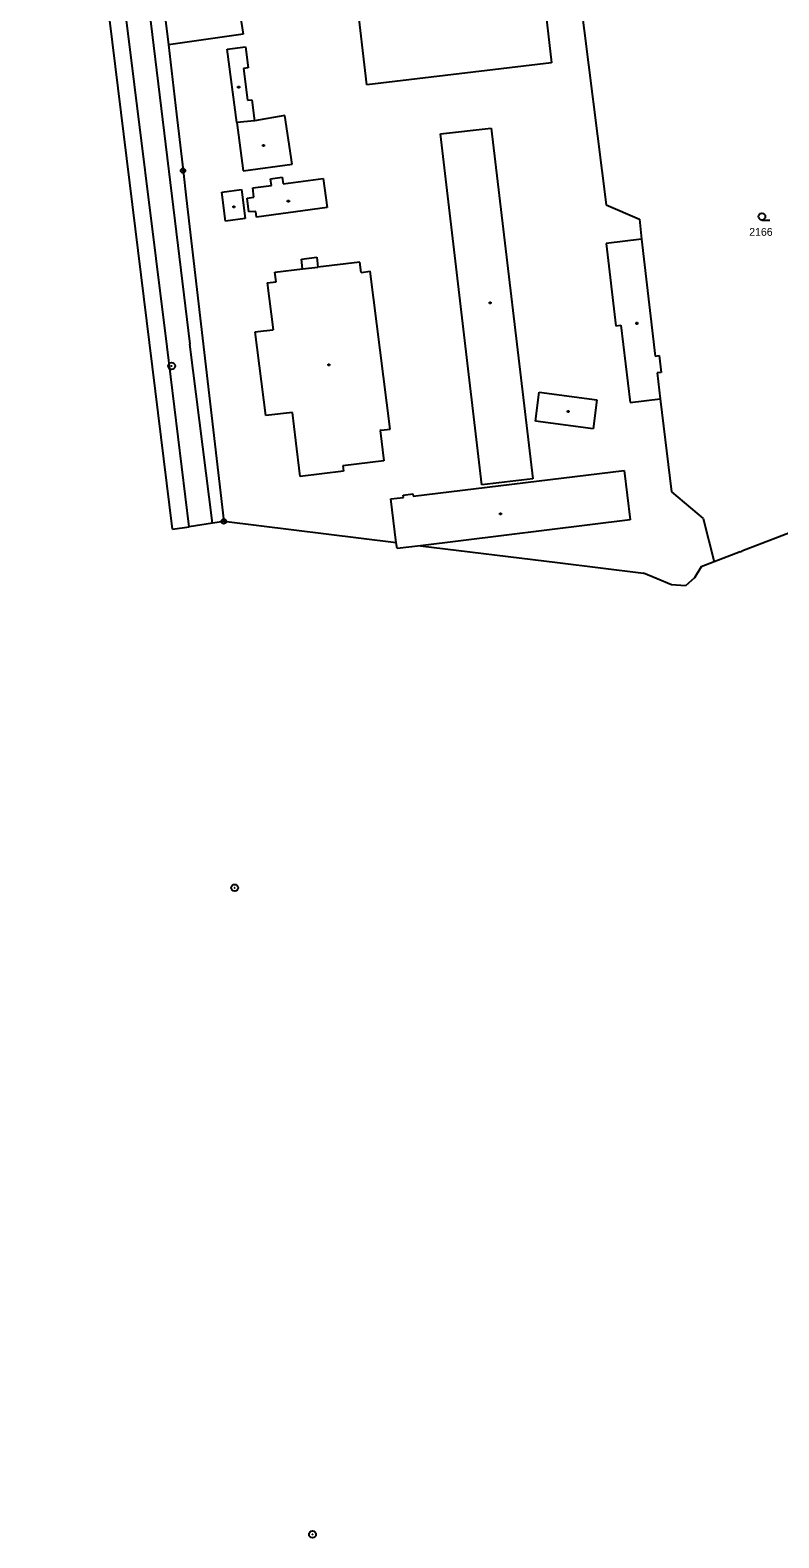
# Model space of a CAD drawing. Extents: x -795483 to -789093, y -1112258 to -1108741.
# Drawn here: x -791769.3 to -791607.3, y -1111747 to -1111421 of the extents above; entities that cross this region are included whole.
import ezdxf

# ---------------------------------------------------------------- set-up
doc = ezdxf.new("R2010")
doc.units = 0
for name, color, linetype in [('Vrstva 1', 7, 'Continuous'), ('Vrstva 14', 7, 'Continuous'), ('Vrstva 2', 7, 'Continuous'), ('Vrstva 23', 7, 'Continuous'), ('Vrstva 25', 7, 'Continuous'), ('Vrstva 28', 7, 'Continuous'), ('Vrstva 3', 7, 'Continuous'), ('Vrstva 4', 7, 'Continuous')]:
    doc.layers.add(name, color=color, linetype=linetype)

msp = doc.modelspace()

# ---------------------------------------------------------------- linework, layer by layer
at = {"layer": 'Vrstva 1'}
for p, q in [((-791744.16, -1111384.45), (-791739.38, -1111424.13)), ((-791653.57, -1111388.05), (-791644.62, -1111458.76)), ((-791723.95, -1111417.3), (-791723.17, -1111421.87)), ((-791723.17, -1111421.87), (-791739.38, -1111424.13)), ((-791739.38, -1111424.13), (-791737.64, -1111439.15)), ((-791737.64, -1111439.15), (-791736.22, -1111451.36)), ((-791736.22, -1111451.36), (-791735.54, -1111457.24)), ((-791735.54, -1111457.24), (-791727.4, -1111527.22)), ((-791644.62, -1111458.76), (-791637.47, -1111461.87)), ((-791637.47, -1111461.87), (-791637.02, -1111466.18)), ((-791637.02, -1111466.18), (-791634.04, -1111491.46)), ((-791634.04, -1111491.46), (-791633.18, -1111491.36)), ((-791633.18, -1111491.36), (-791632.76, -1111494.98)), ((-791632.76, -1111494.98), (-791633.61, -1111495.09)), ((-791633.61, -1111495.09), (-791632.95, -1111500.71)), ((-791632.95, -1111500.71), (-791630.52, -1111520.82)), ((-791630.52, -1111520.82), (-791623.66, -1111526.59)), ((-791623.66, -1111526.59), (-791621.26, -1111535.95))]:
    msp.add_line(p, q, dxfattribs=at)
at = {"layer": 'Vrstva 2'}
for p, q in [((-791769.19, -1111205.07), (-791734.76, -1111488.89)), ((-791739.62, -1111489.46), (-791769.3, -1111251.83)), ((-791660.16, -1111395.95), (-791656.45, -1111428.01)), ((-791696.42, -1111432.77), (-791700.24, -1111400.72)), ((-791726.68, -1111425.07), (-791722.71, -1111424.61)), ((-791724.58, -1111440.91), (-791726.68, -1111425.07)), ((-791722.71, -1111424.61), (-791722.15, -1111429.12)), ((-791722.15, -1111429.12), (-791723.14, -1111429.24)), ((-791723.14, -1111429.24), (-791722.29, -1111436.14)), ((-791656.45, -1111428.01), (-791696.42, -1111432.77)), ((-791722.29, -1111436.14), (-791721.3, -1111436.01)), ((-791721.3, -1111436.01), (-791720.74, -1111440.57)), ((-791714.2, -1111439.4), (-791720.74, -1111440.57)), ((-791712.61, -1111449.97), (-791714.2, -1111439.4)), ((-791720.74, -1111440.57), (-791724.58, -1111440.91)), ((-791724.58, -1111440.91), (-791723.18, -1111451.38)), ((-791680.48, -1111443.43), (-791669.53, -1111442.14)), ((-791669.53, -1111442.14), (-791660.53, -1111517.97)), ((-791671.53, -1111519.27), (-791680.48, -1111443.43)), ((-791723.18, -1111451.38), (-791712.61, -1111449.97)), ((-791717.28, -1111453.15), (-791714.77, -1111452.79)), ((-791717.09, -1111454.56), (-791717.28, -1111453.15)), ((-791714.77, -1111452.79), (-791714.58, -1111454.22)), ((-791714.58, -1111454.22), (-791705.88, -1111453.06)), ((-791705.88, -1111453.06), (-791705.02, -1111459.35)), ((-791727.83, -1111455.99), (-791723.59, -1111455.43)), ((-791727.05, -1111462.29), (-791727.83, -1111455.99)), ((-791723.59, -1111455.43), (-791722.77, -1111461.72)), ((-791721.13, -1111455.1), (-791717.09, -1111454.56)), ((-791720.86, -1111457.1), (-791721.13, -1111455.1)), ((-791722.35, -1111457.29), (-791720.86, -1111457.1)), ((-791721.98, -1111460.28), (-791722.35, -1111457.29)), ((-791705.02, -1111459.35), (-791720.32, -1111461.39)), ((-791722.77, -1111461.72), (-791727.05, -1111462.29)), ((-791720.48, -1111460.17), (-791721.98, -1111460.28)), ((-791720.32, -1111461.39), (-791720.48, -1111460.17)), ((-791637.02, -1111466.18), (-791644.64, -1111467.13)), ((-791644.64, -1111467.13), (-791642.54, -1111484.92)), ((-791716.32, -1111473.3), (-791710.34, -1111472.59)), ((-791710.6, -1111470.47), (-791707.27, -1111470.06)), ((-791710.34, -1111472.59), (-791710.6, -1111470.47)), ((-791710.34, -1111472.59), (-791707.02, -1111472.2)), ((-791707.27, -1111470.06), (-791707.02, -1111472.2)), ((-791697.93, -1111471.13), (-791707.02, -1111472.2)), ((-791697.65, -1111473.36), (-791697.93, -1111471.13)), ((-791718, -1111475.63), (-791716.06, -1111475.39)), ((-791718, -1111475.63), (-791716.73, -1111485.76)), ((-791716.06, -1111475.39), (-791716.32, -1111473.3)), ((-791697.65, -1111473.36), (-791695.71, -1111473.12)), ((-791691.41, -1111507.25), (-791695.71, -1111473.12)), ((-791718.8, -1111486.02), (-791716.73, -1111485.76)), ((-791642.54, -1111484.92), (-791641.47, -1111484.8)), ((-791641.47, -1111484.8), (-791639.49, -1111501.47)), ((-791729.85, -1111527.59), (-791734.76, -1111488.89)), ((-791720.57, -1111486.24), (-791718.8, -1111486.02)), ((-791718.28, -1111504.32), (-791720.57, -1111486.24)), ((-791734.87, -1111528.35), (-791739.62, -1111489.46)), ((-791659.94, -1111505.53), (-791659.12, -1111499.29)), ((-791659.12, -1111499.29), (-791646.64, -1111500.92)), ((-791646.64, -1111500.92), (-791647.46, -1111507.18)), ((-791639.49, -1111501.47), (-791632.95, -1111500.71)), ((-791712.54, -1111503.63), (-791718.28, -1111504.32)), ((-791711.81, -1111509.74), (-791712.54, -1111503.63)), ((-791693.35, -1111507.49), (-791693.57, -1111507.52)), ((-791693.57, -1111507.52), (-791692.76, -1111514.08)), ((-791693.35, -1111507.49), (-791691.41, -1111507.25)), ((-791647.46, -1111507.18), (-791659.94, -1111505.53)), ((-791710.88, -1111517.52), (-791711.81, -1111509.74)), ((-791692.76, -1111514.08), (-791701.67, -1111515.17)), ((-791701.52, -1111516.37), (-791710.88, -1111517.52)), ((-791701.67, -1111515.17), (-791701.52, -1111516.37)), ((-791686.45, -1111521.77), (-791640.76, -1111516.19)), ((-791660.53, -1111517.97), (-791671.53, -1111519.27)), ((-791640.76, -1111516.19), (-791639.45, -1111526.89)), ((-791688.59, -1111521.52), (-791686.52, -1111521.26)), ((-791688.53, -1111522.02), (-791688.59, -1111521.52)), ((-791686.52, -1111521.26), (-791686.45, -1111521.77)), ((-791691.22, -1111522.35), (-791688.53, -1111522.02)), ((-791690.06, -1111531.82), (-791691.22, -1111522.35)), ((-791639.45, -1111526.89), (-791684.82, -1111532.47))]:
    msp.add_line(p, q, dxfattribs=at)
at = {"layer": 'Vrstva 23'}
msp.add_line((-791610.96, -1111462.03), (-791609.21, -1111462.03), dxfattribs=at)
msp.add_circle((-791610.96, -1111461.28), 0.75, dxfattribs=at)
at = {"layer": 'Vrstva 25'}
for p, q in [((-791724.32, -1111433.14), (-791724.02, -1111433.14)), ((-791724.32, -1111433.44), (-791724.32, -1111433.14)), ((-791724.02, -1111433.44), (-791724.32, -1111433.44)), ((-791724.02, -1111433.14), (-791724.02, -1111433.44)), ((-791718.95, -1111445.75), (-791718.65, -1111445.75)), ((-791718.95, -1111446.05), (-791718.95, -1111445.75)), ((-791718.65, -1111446.05), (-791718.95, -1111446.05)), ((-791718.65, -1111445.75), (-791718.65, -1111446.05)), ((-791725.37, -1111459.06), (-791725.07, -1111459.06)), ((-791725.37, -1111459.36), (-791725.37, -1111459.06)), ((-791725.07, -1111459.36), (-791725.37, -1111459.36)), ((-791725.07, -1111459.06), (-791725.07, -1111459.36)), ((-791713.58, -1111457.78), (-791713.28, -1111457.78)), ((-791713.58, -1111458.08), (-791713.58, -1111457.78)), ((-791713.28, -1111458.08), (-791713.58, -1111458.08)), ((-791713.28, -1111457.78), (-791713.28, -1111458.08)), ((-791669.93, -1111479.78), (-791669.63, -1111479.78)), ((-791669.93, -1111480.08), (-791669.93, -1111479.78)), ((-791669.63, -1111480.08), (-791669.93, -1111480.08)), ((-791669.63, -1111479.78), (-791669.63, -1111480.08)), ((-791638.18, -1111484.22), (-791637.88, -1111484.22)), ((-791638.18, -1111484.52), (-791638.18, -1111484.22)), ((-791637.88, -1111484.52), (-791638.18, -1111484.52)), ((-791637.88, -1111484.22), (-791637.88, -1111484.52)), ((-791704.83, -1111493.21), (-791704.53, -1111493.21)), ((-791704.83, -1111493.51), (-791704.83, -1111493.21)), ((-791704.53, -1111493.51), (-791704.83, -1111493.51)), ((-791704.53, -1111493.21), (-791704.53, -1111493.51)), ((-791653.03, -1111503.27), (-791652.73, -1111503.27)), ((-791653.03, -1111503.57), (-791653.03, -1111503.27)), ((-791652.73, -1111503.57), (-791653.03, -1111503.57)), ((-791652.73, -1111503.27), (-791652.73, -1111503.57)), ((-791667.68, -1111525.45), (-791667.38, -1111525.45)), ((-791667.68, -1111525.75), (-791667.68, -1111525.45)), ((-791667.38, -1111525.75), (-791667.68, -1111525.75)), ((-791667.38, -1111525.45), (-791667.38, -1111525.75))]:
    msp.add_line(p, q, dxfattribs=at)
at = {"layer": 'Vrstva 28'}
for centre, radius in [((-791736.22, -1111451.36), 0.5), ((-791736.22, -1111451.36), 0.01), ((-791738.7, -1111493.6), 0.75), ((-791738.7, -1111493.6), 0.01), ((-791727.4, -1111527.22), 0.5), ((-791727.4, -1111527.22), 0.01), ((-791725.04, -1111606.44), 0.75), ((-791725.04, -1111606.44), 0.01), ((-791708.2, -1111746.26), 0.75), ((-791708.2, -1111746.26), 0.01)]:
    msp.add_circle(centre, radius, dxfattribs=at)
at = {"layer": 'Vrstva 3'}
for p, q in [((-791562.26, -1111513.18), (-791615.27, -1111533.63)), ((-791729.85, -1111527.59), (-791734.87, -1111528.35)), ((-791727.4, -1111527.22), (-791729.85, -1111527.59)), ((-791690.06, -1111531.82), (-791727.4, -1111527.22)), ((-791738.46, -1111528.89), (-791734.87, -1111528.35)), ((-791689.9, -1111533.09), (-791690.06, -1111531.82)), ((-791684.82, -1111532.47), (-791689.9, -1111533.09)), ((-791684.82, -1111532.47), (-791655.19, -1111536.12)), ((-791615.66, -1111533.78), (-791621.26, -1111535.95)), ((-791615.66, -1111533.78), (-791615.27, -1111533.63)), ((-791655.19, -1111536.12), (-791636.59, -1111538.41)), ((-791624.1, -1111537.05), (-791625.55, -1111539.41)), ((-791621.26, -1111535.95), (-791624.1, -1111537.05)), ((-791633.62, -1111539.65), (-791636.59, -1111538.41)), ((-791630.5, -1111540.94), (-791633.62, -1111539.65)), ((-791627.51, -1111541.15), (-791630.5, -1111540.94)), ((-791625.55, -1111539.41), (-791627.51, -1111541.15))]:
    msp.add_line(p, q, dxfattribs=at)
at = {"layer": 'Vrstva 4'}
msp.add_line((-791738.46, -1111528.89), (-791767.93, -1111290.13), dxfattribs=at)

# ---------------------------------------------------------------- texts
at = {"layer": 'Vrstva 14'}
msp.add_text('2166', height=1.7, dxfattribs=at).set_placement((-791613.69, -1111465.45))

doc.saveas('drawing.dxf')
